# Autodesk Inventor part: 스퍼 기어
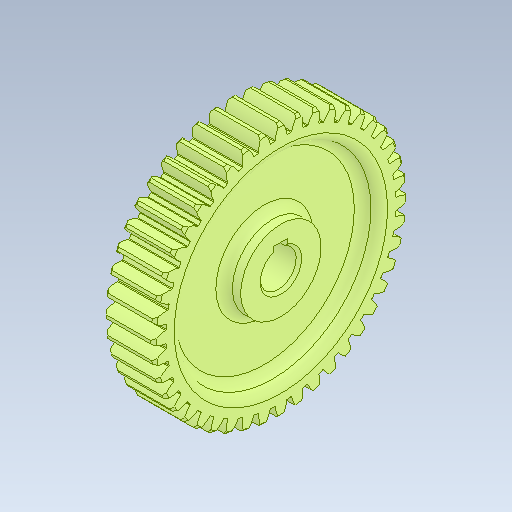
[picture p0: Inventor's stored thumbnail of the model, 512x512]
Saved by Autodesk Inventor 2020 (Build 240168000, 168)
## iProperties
Created: 2024-08
Part Number: 스퍼 기어
Material: 강철, 탄소
Document SubType Name: Modeling
Designer: oem
Density: 7.85 g/cm^3
Appearance: 기본값
Author: jhkim
Sending System: Autodesk Inventor 2025
Preprocessor: ST-DEVELOPER v20
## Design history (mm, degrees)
node "스퍼 기어1"
node "솔리드2"
node "솔리드1"
